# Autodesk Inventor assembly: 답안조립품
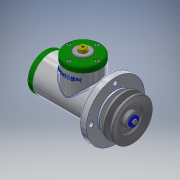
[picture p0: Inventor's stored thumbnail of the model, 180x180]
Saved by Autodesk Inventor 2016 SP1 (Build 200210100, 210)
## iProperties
Created: 2016-08
Part Number: 답안조립품
Material: 일반
Document SubType Name: Assembly
Designer: basic
Author: basic
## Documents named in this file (25)
- C:\Users\basic\Desktop\460808V1009\답안조립품.iam
- C:\Users\basic\Desktop\460808V1009\본체.ipt
- C:\Users\basic\Desktop\460808V1009\사이드 커버.ipt
- 사이드 커버.ipt
- C:\Users\basic\Desktop\460808V1009\탑 커버.ipt
- 탑 커버.ipt
- C:\Users\basic\Desktop\460808V1009\베어링 15 x 35 x 11.ipt
- C:\Users\basic\Desktop\460808V1009\멈춤링 35x1.6.ipt
- C:\Users\basic\Desktop\460808V1009\편심축.ipt
- C:\Users\basic\Desktop\460808V1009\슬라이더.ipt
- C:\Users\basic\Desktop\460808V1009\탑 부시.ipt
- C:\Users\basic\Desktop\460808V1009\클래스터 핀 6 x 24.ipt
- C:\Users\basic\Desktop\460808V1009\링크.ipt
- C:\Users\basic\Desktop\460808V1009\키 4 x 4 x 18.ipt
- C:\Users\basic\Desktop\460808V1009\멈춤링 15 x 1.ipt
- C:\Users\basic\Desktop\460808V1009\오일 실 15 25 7.ipt
- C:\Users\basic\Desktop\460808V1009\와셔 10x21.ipt
- C:\Users\basic\Desktop\460808V1009\너트 M10.ipt
- C:\Users\basic\Desktop\460808V1009\부시2.ipt
- C:\Users\basic\Desktop\460808V1009\부시1.ipt
- C:\Users\basic\Desktop\460808V1009\와셔 4x16.ipt
- C:\Users\basic\Desktop\460808V1009\V-벨트풀리.ipt
- C:\Users\basic\Desktop\460808V1009\볼트 M4 x 10.ipt
- C:\Users\basic\Desktop\460808V1009\분할핀 1.6 x 12.ipt
- C:\Users\basic\Desktop\460808V1009\볼트 M4 x 12.ipt
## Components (6 placed, 3 different names)
1. V-벨트풀리:1
2. ISO 4017 M4 x 10:1
3. ISO 4762 M4 x 12:1
4. ISO 4762 M4 x 12:2
5. ISO 4762 M4 x 12:3
6. ISO 4762 M4 x 12:4
